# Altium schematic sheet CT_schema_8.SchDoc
size 741 x 377 mm
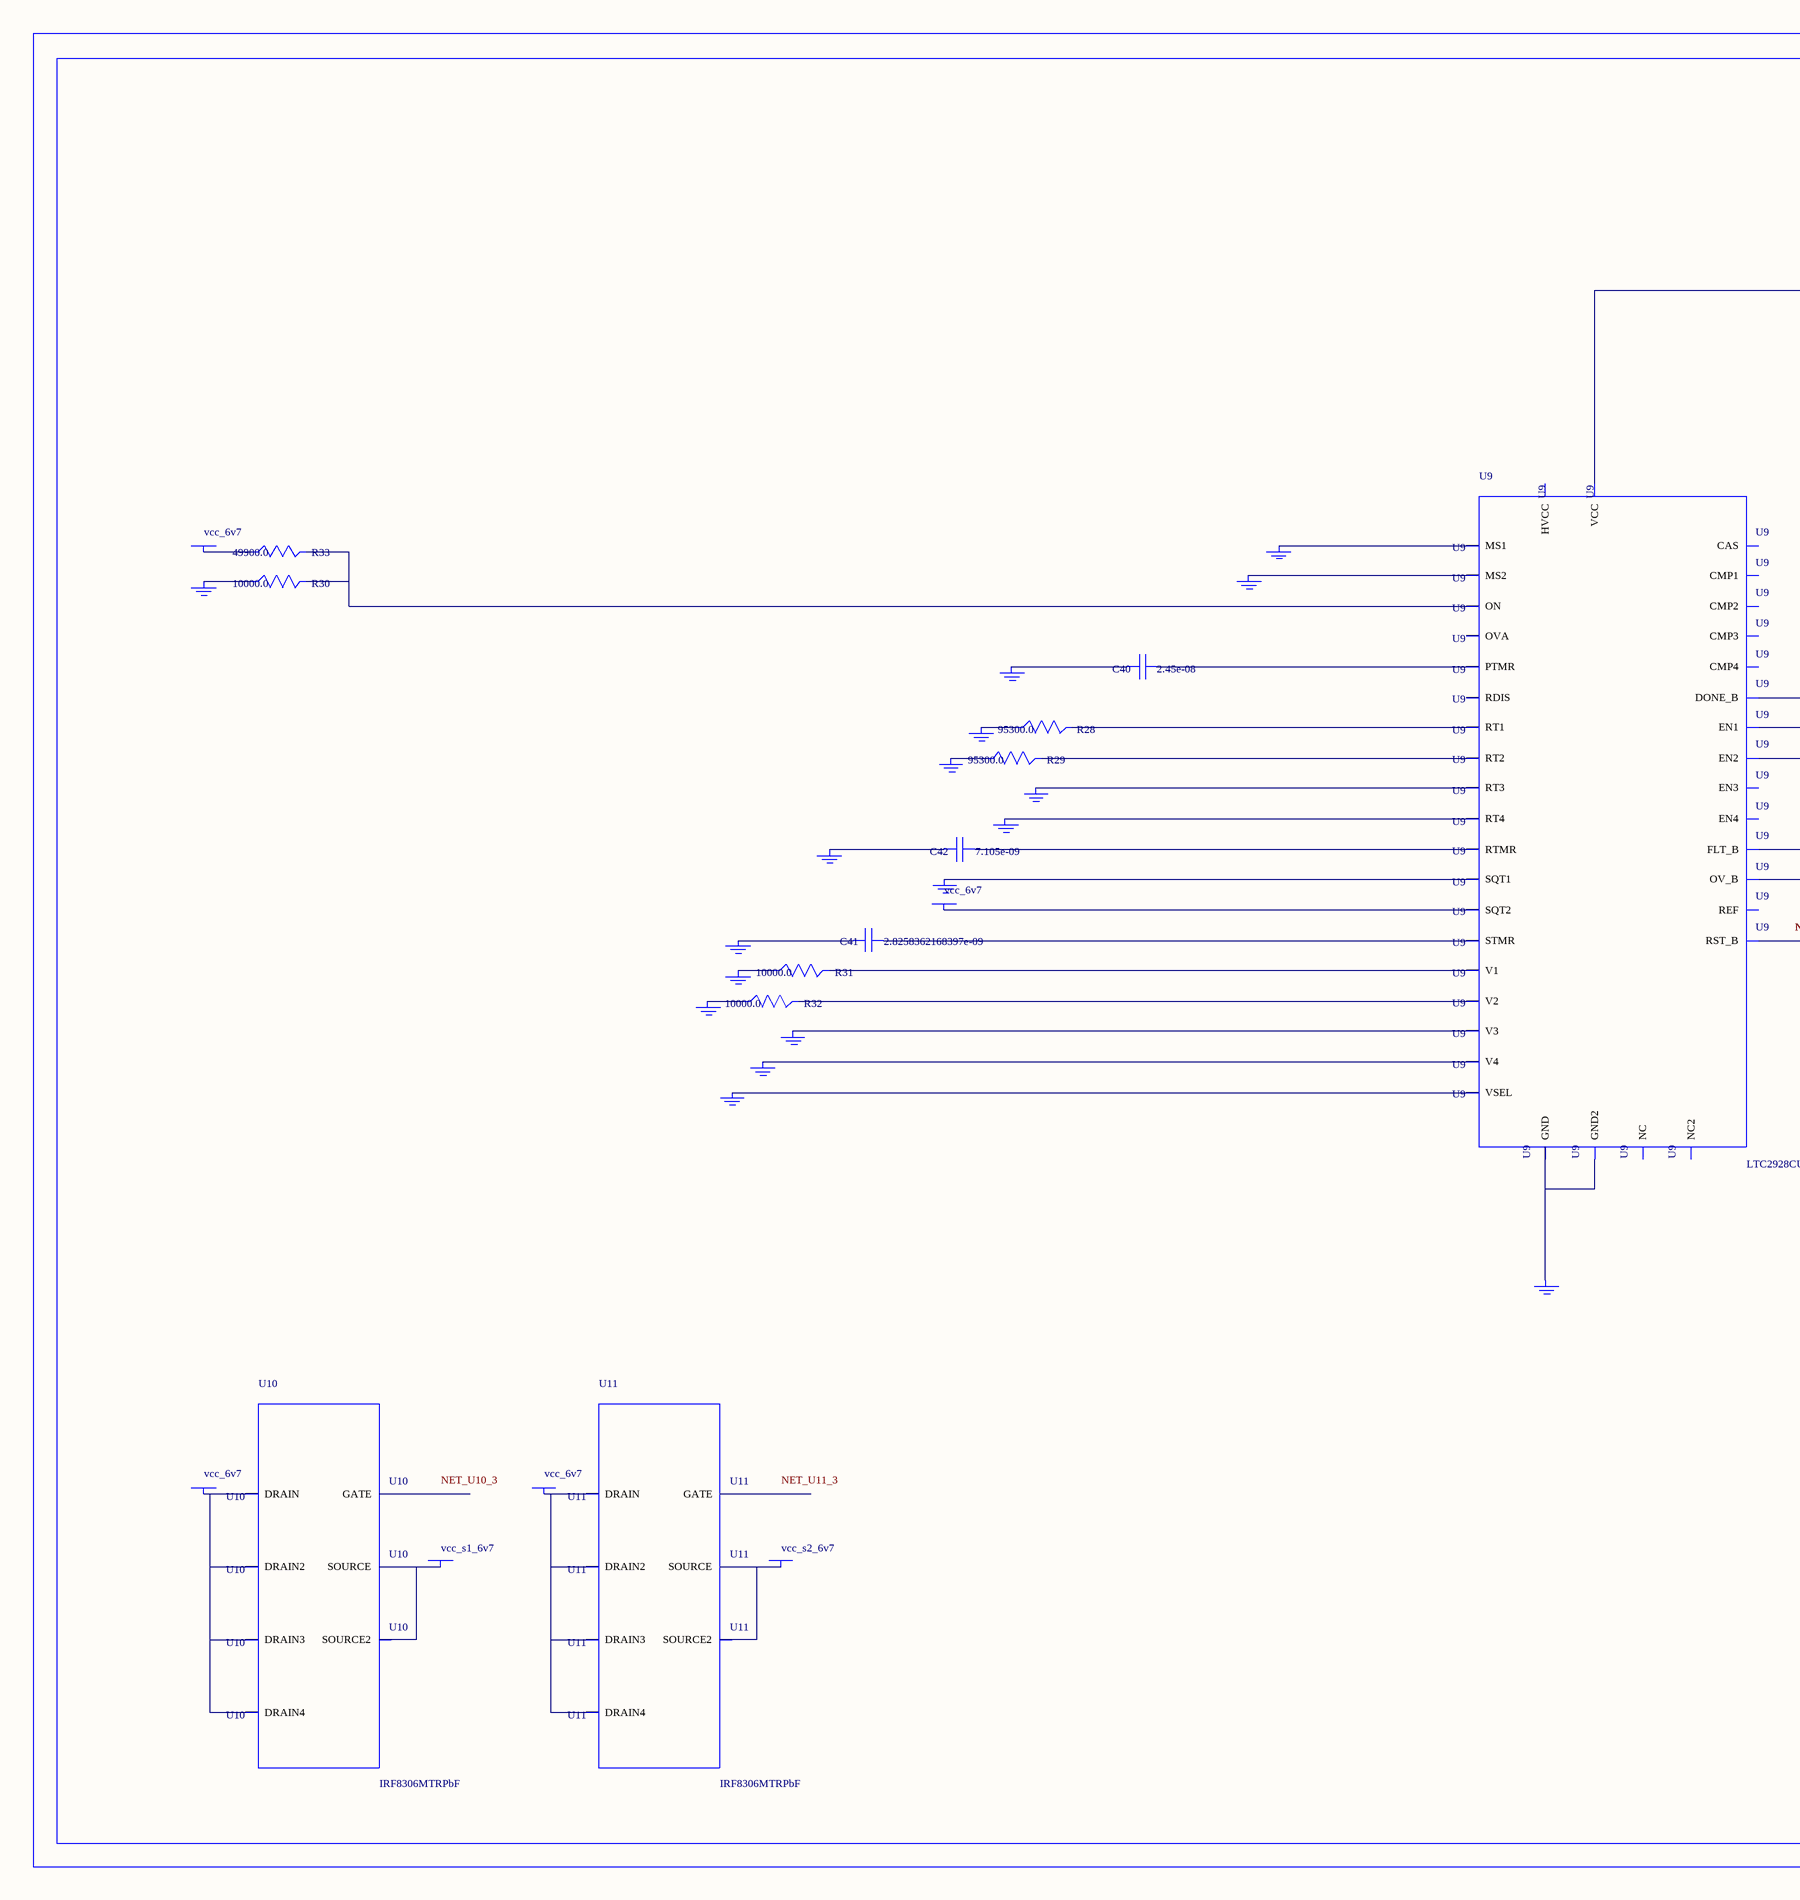
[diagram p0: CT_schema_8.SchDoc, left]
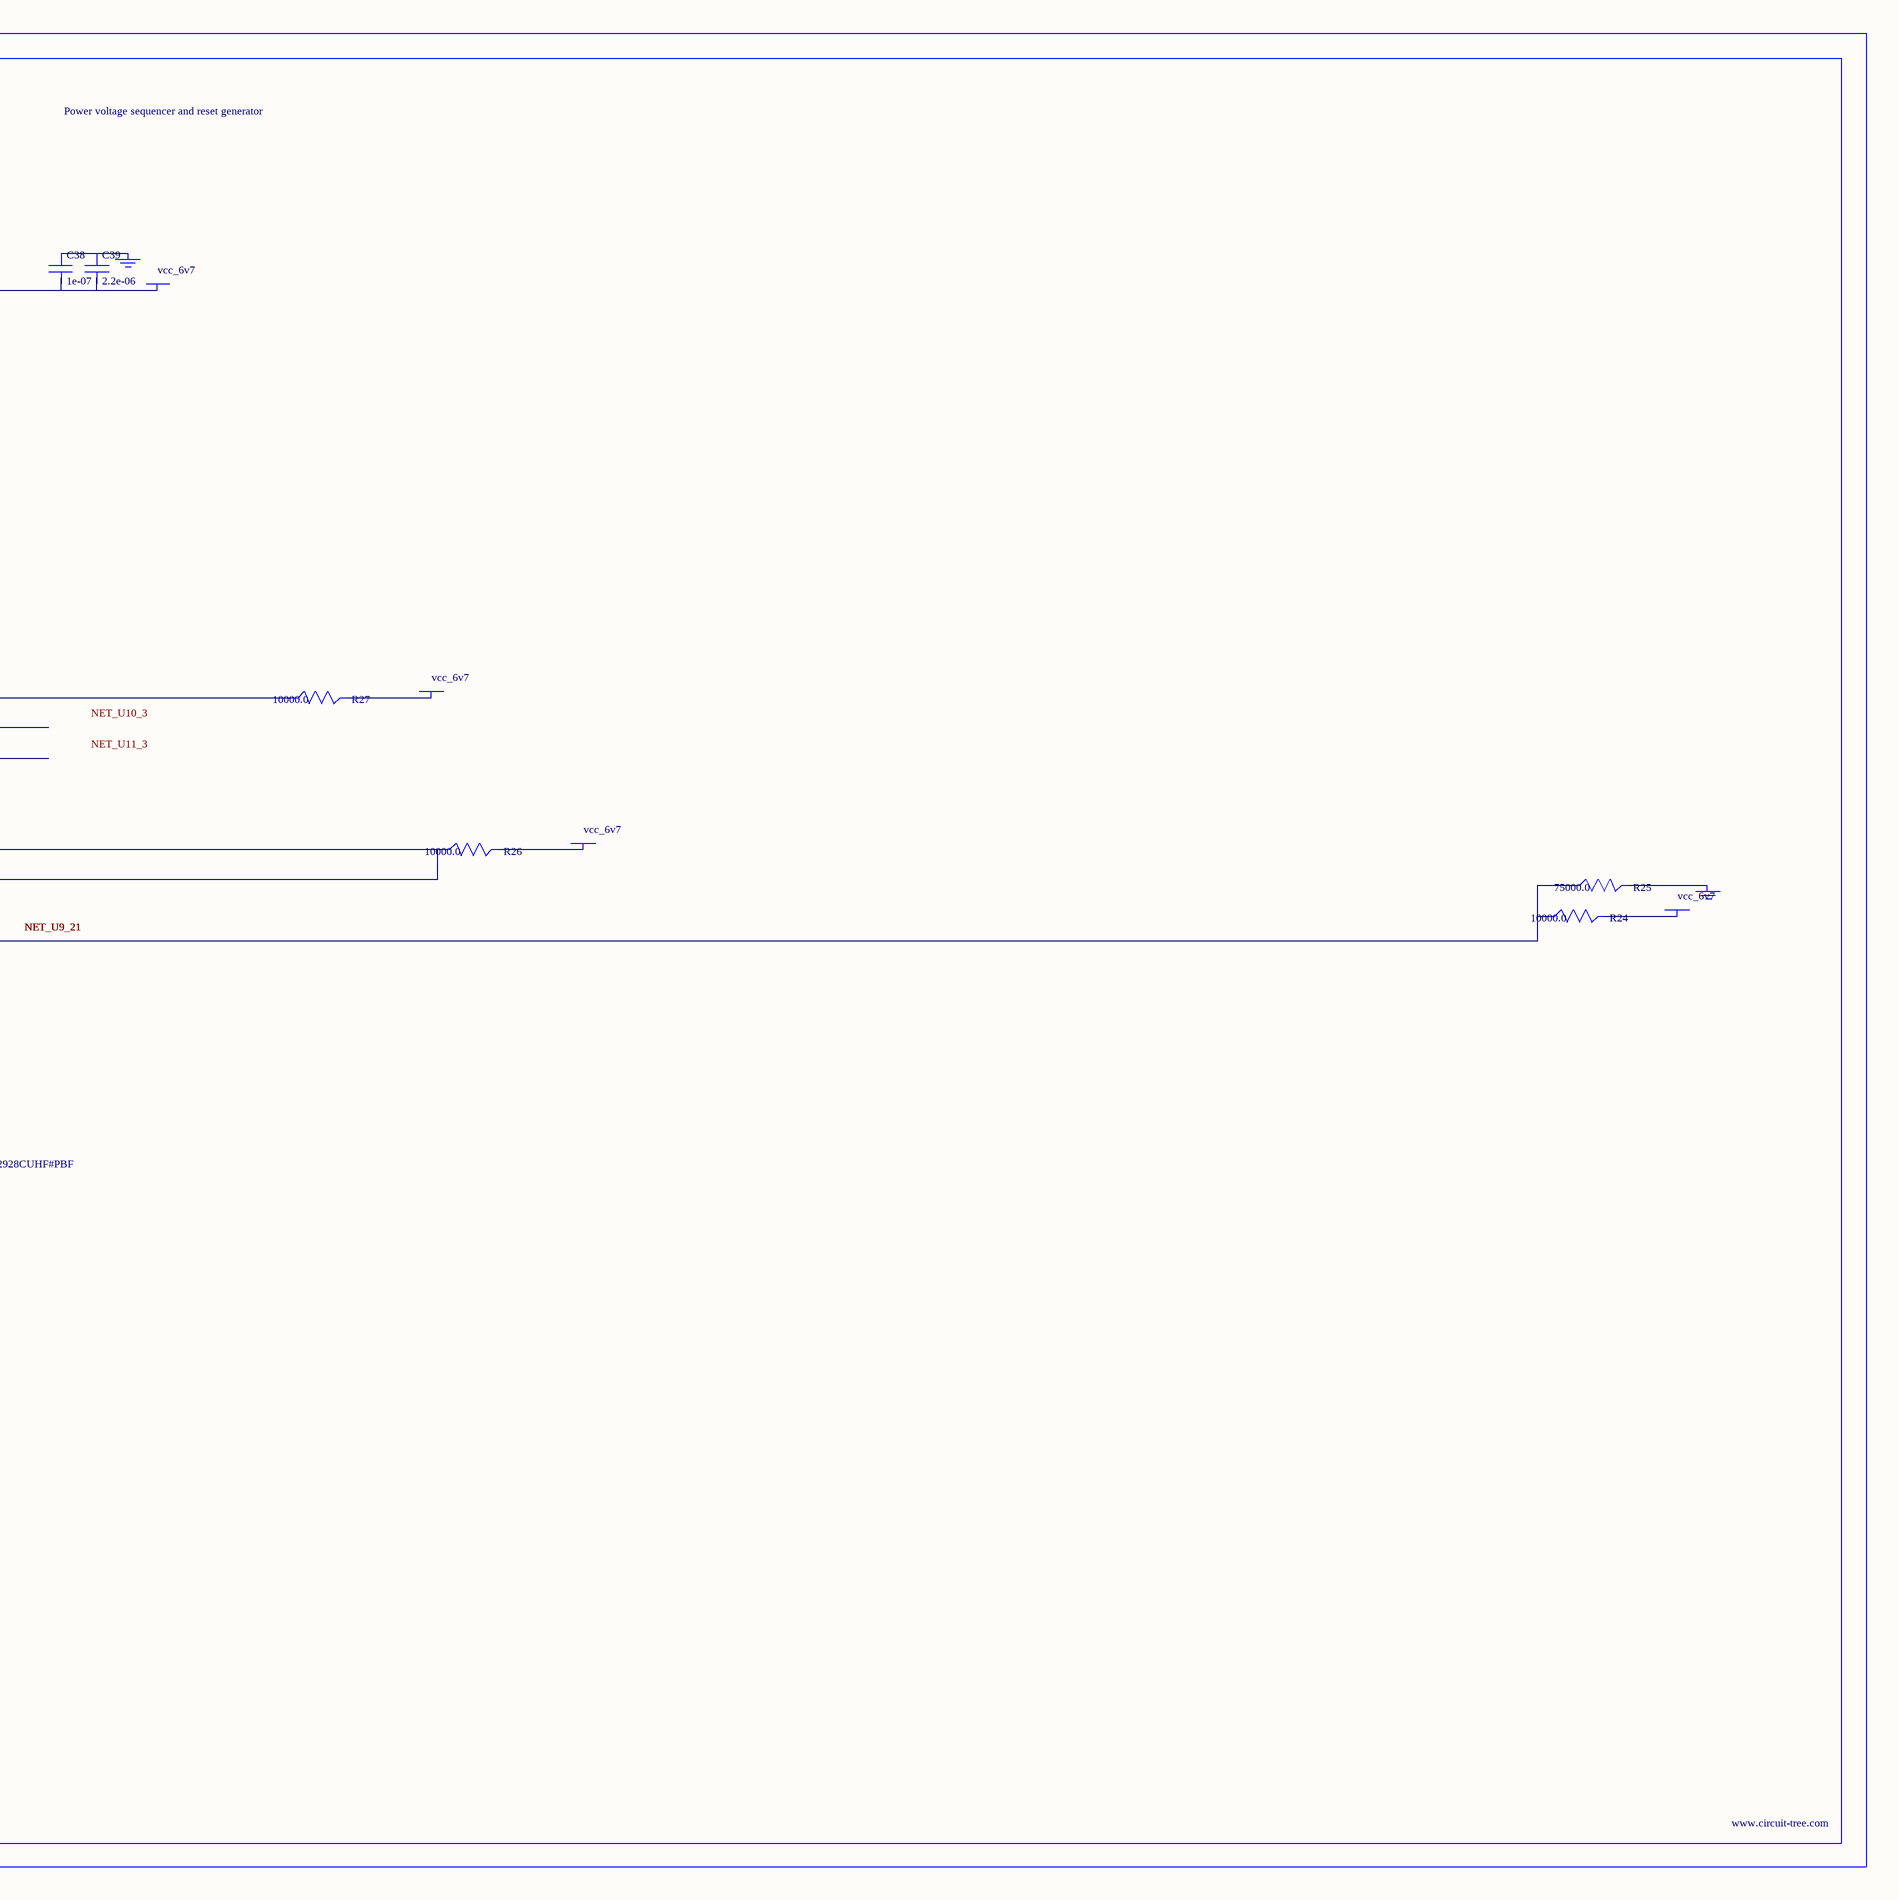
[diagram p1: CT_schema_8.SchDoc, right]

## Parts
BORDER7  (no value)
C38  1e-07  [C0402]
C39  2.2e-06  [C0603]
C40  2.45e-08  [R0603]
C41  2.8258362168397e-09  [R0603]
C42  7.105e-09  [R0603]
GND_INSTANCE_7_0  (no value)
GND_INSTANCE_7_1  (no value)
GND_INSTANCE_7_2  (no value)
GND_INSTANCE_7_3  (no value)
GND_INSTANCE_7_4  (no value)
GND_INSTANCE_7_5  (no value)
GND_INSTANCE_7_6  (no value)
GND_INSTANCE_7_7  (no value)
GND_INSTANCE_7_8  (no value)
GND_INSTANCE_7_9  (no value)
GND_INSTANCE_7_10  (no value)
GND_INSTANCE_7_11  (no value)
GND_INSTANCE_7_12  (no value)
GND_INSTANCE_7_13  (no value)
GND_INSTANCE_7_14  (no value)
GND_INSTANCE_7_15  (no value)
GND_INSTANCE_7_16  (no value)
GND_INSTANCE_7_17  (no value)
GND_INSTANCE_7_18  (no value)
POWER_INSTANCE_7_0  vcc_6v7
POWER_INSTANCE_7_1  vcc_6v7
POWER_INSTANCE_7_2  vcc_6v7
POWER_INSTANCE_7_3  vcc_6v7
POWER_INSTANCE_7_4  vcc_6v7
POWER_INSTANCE_7_5  vcc_6v7
POWER_INSTANCE_7_6  vcc_6v7
POWER_INSTANCE_7_7  vcc_s1_6v7
POWER_INSTANCE_7_8  vcc_6v7
POWER_INSTANCE_7_9  vcc_s2_6v7
R24  10000.0  [R0603]
R25  75000.0  [R0603]
R26  10000.0  [R0603]
R27  10000.0  [R0603]
R28  95300.0  [R0603]
R29  95300.0  [R0603]
R30  10000.0  [R0603]
R31  10000.0  [R0603]
R32  10000.0  [R0603]
R33  49900.0  [R0603]
U9  LTC2928CUHF#PBF  [QFN-38_UHF]
U10  IRF8306MTRPbF  [IRF8306MTRPBF]
U11  IRF8306MTRPbF  [IRF8306MTRPBF]

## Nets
NetC38_1: C38.1 C39.1 GND_INSTANCE_7_10.0(GND)
NetC38_2: C38.2 C39.2 POWER_INSTANCE_7_5.0(PWR) U9.22(VCC)
NetC40_1: C40.1 U9.27(PTMR)
NetC40_2: C40.2 GND_INSTANCE_7_13.0(GND)
NetC41_1: C41.1 U9.26(STMR)
NetC41_2: C41.2 GND_INSTANCE_7_12.0(GND)
NetC42_1: C42.1 U9.28(RTMR)
NetC42_2: C42.2 GND_INSTANCE_7_14.0(GND)
NetGND_INSTANCE_7_0_0: GND_INSTANCE_7_0.0(GND) R31.1
NetGND_INSTANCE_7_1_0: GND_INSTANCE_7_1.0(GND) R28.1
NetGND_INSTANCE_7_2_0: GND_INSTANCE_7_2.0(GND) R29.1
NetGND_INSTANCE_7_3_0: GND_INSTANCE_7_3.0(GND) U9.8(RT3)
NetGND_INSTANCE_7_4_0: GND_INSTANCE_7_4.0(GND) U9.9(RT4)
NetGND_INSTANCE_7_5_0: GND_INSTANCE_7_5.0(GND) U9.10(SQT1)
NetGND_INSTANCE_7_6_0: GND_INSTANCE_7_6.0(GND) U9.12(MS1)
NetGND_INSTANCE_7_7_0: GND_INSTANCE_7_7.0(GND) U9.13(MS2)
NetGND_INSTANCE_7_8_0: GND_INSTANCE_7_8.0(GND) R30.1
NetGND_INSTANCE_7_9_0: GND_INSTANCE_7_9.0(GND) R25.2
NetGND_INSTANCE_7_11_0: GND_INSTANCE_7_11.0(GND) U9.25(VSEL)
NetGND_INSTANCE_7_15_0: GND_INSTANCE_7_15.0(GND) U9.30(V4)
NetGND_INSTANCE_7_16_0: GND_INSTANCE_7_16.0(GND) U9.32(V3)
NetGND_INSTANCE_7_17_0: GND_INSTANCE_7_17.0(GND) R32.1
NetGND_INSTANCE_7_18_0: GND_INSTANCE_7_18.0(GND) U9.24(GND) U9.39(GND2)
NetPOWER_INSTANCE_7_0_0: POWER_INSTANCE_7_0.0(PWR) U9.11(SQT2)
NetPOWER_INSTANCE_7_1_0: POWER_INSTANCE_7_1.0(PWR) R33.1
NetPOWER_INSTANCE_7_2_0: POWER_INSTANCE_7_2.0(PWR) R27.2
NetPOWER_INSTANCE_7_3_0: POWER_INSTANCE_7_3.0(PWR) R26.2
NetPOWER_INSTANCE_7_4_0: POWER_INSTANCE_7_4.0(PWR) R24.2
NetPOWER_INSTANCE_7_6_0: POWER_INSTANCE_7_6.0(PWR) U10.1(DRAIN) U10.2(DRAIN2) U10.6(DRAIN3) U10.7(DRAIN4)
NetPOWER_INSTANCE_7_7_0: POWER_INSTANCE_7_7.0(PWR) U10.4(SOURCE) U10.5(SOURCE2)
NetPOWER_INSTANCE_7_8_0: POWER_INSTANCE_7_8.0(PWR) U11.1(DRAIN) U11.2(DRAIN2) U11.6(DRAIN3) U11.7(DRAIN4)
NetPOWER_INSTANCE_7_9_0: POWER_INSTANCE_7_9.0(PWR) U11.4(SOURCE) U11.5(SOURCE2)
NetR24_1: R24.1 R25.1 U9.21(RST_B)
NetR26_1: R26.1 U9.19(FLT_B) U9.20(OV_B)
NetR27_1: R27.1 U9.18(DONE_B)
NetR28_2: R28.2 U9.6(RT1)
NetR29_2: R29.2 U9.7(RT2)
NetR30_2: R30.2 R33.2 U9.16(ON)
NetR31_2: R31.2 U9.3(V1)
NetR32_2: R32.2 U9.38(V2)

Not connected (* = marked no-connect by the designer): U9 1(OVA) 2(EN1) 4(NC) 5(REF) 14(RDIS) 15(CAS) 17(NC2) 23(HVCC) 29(EN4) 31(EN3) 33(CMP3) 34(CMP4) 35(CMP1) 36(CMP2) 37(EN2); U10 3(GATE); U11 3(GATE)

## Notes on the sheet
- Labels drawn without touching a wire or pin: NET_U10_3, NET_U11_3

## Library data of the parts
BORDER7 = BORDER_PAGE7
C38 = C0402C104K3RACTU
C39 = GRM188R61H225KE1115D
C40 = C40
C41 = C41
C42 = C42
GND_INSTANCE_7_0-GND_INSTANCE_7_18 = GND
POWER_INSTANCE_7_0-POWER_INSTANCE_7_9 = PWR
R24 R26 R27 R30-R32 = RC0603JR-0710KL
R25 = RC0603JR-0775KL
R28 R29 = RC0603FR-0795K3L
R33 = RC0603FR-0749K9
